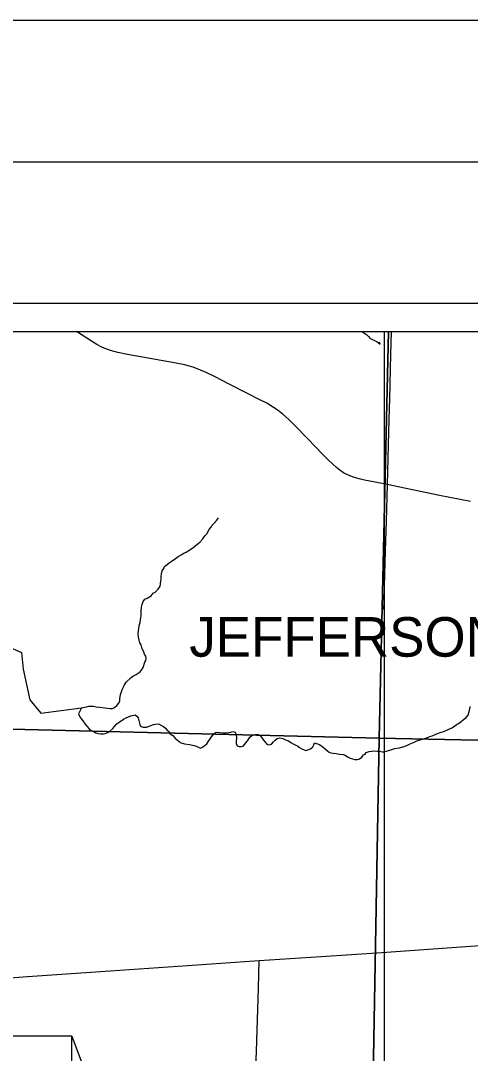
# Model space of a CAD drawing. Extents: x -21.9 to 47.3, y 14.1 to 48.7.
# Drawn here: x 4.214 to 5.806, y 45.08 to 48.733 of the extents above; entities that cross this region are included whole.
import ezdxf

# ---------------------------------------------------------------- set-up
doc = ezdxf.new("R2010")
doc.units = 0
for name, color, linetype in [('Default', 7, 'Continuous'), ('GM_X_County_Road', 7, 'Continuous'), ('GM_X_Minor_River', 7, 'Continuous'), ('GM_X_Section', 7, 'Continuous'), ('GM_X_Township_Road', 7, 'Continuous'), ('GM_X_US_Route', 7, 'Continuous'), ('SC_Scratch1', 7, 'Continuous'), ('SH_Border', 7, 'Continuous'), ('SH_Cut_Line', 7, 'Continuous'), ('SH_Data', 7, 'Continuous'), ('SH_Text', 7, 'Continuous')]:
    doc.layers.add(name, color=color, linetype=linetype)

msp = doc.modelspace()

# ---------------------------------------------------------------- linework, layer by layer
at = {"layer": 'Default'}
msp.add_lwpolyline([(2.8572, 44.6473), (4.3955, 44.6473), (4.3955, 45.1408), (2.8572, 45.1408)], close=True, dxfattribs=at)
at = {"layer": 'GM_X_County_Road'}
for p, q in [((4.4644, 47.5992), (4.4115, 47.6334)), ((4.4836, 47.5878), (4.4644, 47.5992)), ((4.5011, 47.5786), (4.4836, 47.5878)), ((4.51, 47.5745), (4.5011, 47.5786)), ((4.5318, 47.566), (4.51, 47.5745)), ((4.558, 47.5589), (4.5318, 47.566)), ((4.592, 47.552), (4.558, 47.5589)), ((4.6788, 47.5365), (4.592, 47.552)), ((4.7643, 47.5213), (4.6788, 47.5365)), ((4.7948, 47.5152), (4.7643, 47.5213)), ((4.8074, 47.5123), (4.7948, 47.5152)), ((4.8249, 47.507), (4.8074, 47.5123)), ((4.8505, 47.4971), (4.8249, 47.507)), ((4.871, 47.4881), (4.8505, 47.4971)), ((4.9023, 47.4727), (4.871, 47.4881)), ((4.9522, 47.4474), (4.9023, 47.4727)), ((5.022, 47.412), (4.9522, 47.4474)), ((5.0586, 47.3935), (5.022, 47.412)), ((5.0849, 47.3795), (5.0586, 47.3935)), ((5.1053, 47.3674), (5.0849, 47.3795)), ((5.125, 47.3541), (5.1053, 47.3674)), ((5.1436, 47.3394), (5.125, 47.3541)), ((5.163, 47.3218), (5.1436, 47.3394)), ((5.1871, 47.2984), (5.163, 47.3218)), ((5.2272, 47.2576), (5.1871, 47.2984)), ((5.2615, 47.2217), (5.2272, 47.2576)), ((5.2805, 47.202), (5.2615, 47.2217)), ((5.3024, 47.18), (5.2805, 47.202)), ((5.3193, 47.1637), (5.3024, 47.18)), ((5.3313, 47.153), (5.3193, 47.1637)), ((5.3437, 47.1429), (5.3313, 47.153)), ((5.357, 47.1339), (5.3437, 47.1429)), ((5.3633, 47.1302), (5.357, 47.1339)), ((5.3787, 47.1226), (5.3633, 47.1302)), ((5.3961, 47.1166), (5.3787, 47.1226)), ((5.4116, 47.1123), (5.3961, 47.1166)), ((5.4309, 47.1079), (5.4116, 47.1123)), ((5.5118, 47.0922), (5.4309, 47.1079)), ((5.5276, 47.0889), (5.5118, 47.0922)), ((5.6966, 47.0538), (5.5276, 47.0889)), ((5.8064, 47.0323), (5.6966, 47.0538))]:
    msp.add_line(p, q, dxfattribs=at)
at = {"layer": 'GM_X_Minor_River'}
for p, q in [((5.4218, 47.6334), (5.4387, 47.622)), ((5.4387, 47.622), (5.4446, 47.6165)), ((5.4446, 47.6165), (5.4512, 47.6094)), ((5.4512, 47.6094), (5.4572, 47.607)), ((5.4572, 47.607), (5.4684, 47.6005)), ((5.4684, 47.6005), (5.4744, 47.598)), ((5.4744, 47.598), (5.4862, 47.5885)), ((5.4862, 47.5885), (5.4841, 47.5954)), ((4.8915, 46.9487), (4.8993, 46.956)), ((4.8993, 46.956), (4.908, 46.9664)), ((4.908, 46.9664), (4.9136, 46.9746)), ((4.866, 46.9107), (4.8746, 46.9188)), ((4.8746, 46.9188), (4.8803, 46.9315)), ((4.8803, 46.9315), (4.8867, 46.9405)), ((4.8867, 46.9405), (4.8915, 46.9487)), ((4.8306, 46.8739), (4.8376, 46.8797)), ((4.8376, 46.8797), (4.8478, 46.8885)), ((4.8478, 46.8885), (4.8588, 46.9003)), ((4.8588, 46.9003), (4.866, 46.9107)), ((4.771, 46.837), (4.7818, 46.8435)), ((4.7818, 46.8435), (4.7919, 46.8493)), ((4.7919, 46.8493), (4.7996, 46.8528)), ((4.7996, 46.8528), (4.8073, 46.8579)), ((4.8073, 46.8579), (4.8229, 46.8688)), ((4.8229, 46.8688), (4.8306, 46.8739)), ((4.7228, 46.8021), (4.7321, 46.8087)), ((4.7321, 46.8087), (4.7391, 46.8153)), ((4.7391, 46.8153), (4.7461, 46.8204)), ((4.7461, 46.8204), (4.7617, 46.8305)), ((4.7617, 46.8305), (4.771, 46.837)), ((4.7118, 46.7667), (4.7128, 46.7758)), ((4.7128, 46.7758), (4.7147, 46.7864)), ((4.7147, 46.7864), (4.7203, 46.7946)), ((4.7203, 46.7946), (4.7228, 46.8021)), ((4.7004, 46.7222), (4.7076, 46.7326)), ((4.7076, 46.7326), (4.7104, 46.75)), ((4.7104, 46.75), (4.7114, 46.7569)), ((4.7114, 46.7569), (4.7118, 46.7667)), ((4.6622, 46.69), (4.6754, 46.6987)), ((4.6754, 46.6987), (4.6833, 46.7076)), ((4.6833, 46.7076), (4.6902, 46.7111)), ((4.6902, 46.7111), (4.7004, 46.7222)), ((4.6422, 46.658), (4.644, 46.6678)), ((4.644, 46.6678), (4.6474, 46.6783)), ((4.6474, 46.6783), (4.653, 46.6865)), ((4.653, 46.6865), (4.6622, 46.69)), ((4.6394, 46.6208), (4.6404, 46.6276)), ((4.6404, 46.6276), (4.641, 46.6451)), ((4.641, 46.6451), (4.6422, 46.658)), ((4.6321, 46.5837), (4.6341, 46.5966)), ((4.6341, 46.5966), (4.6366, 46.6041)), ((4.6366, 46.6041), (4.6385, 46.6147)), ((4.6385, 46.6147), (4.6394, 46.6208)), ((4.63, 46.564), (4.6311, 46.5746)), ((4.6311, 46.5518), (4.63, 46.564)), ((4.6311, 46.5746), (4.6321, 46.5837)), ((4.633, 46.5419), (4.6311, 46.5518)), ((4.1656, 46.5198), (4.2174, 46.4977)), ((4.6358, 46.5326), (4.633, 46.5419)), ((4.6401, 46.5256), (4.6358, 46.5326)), ((4.6441, 46.5103), (4.6401, 46.5256)), ((4.2174, 46.4977), (4.223, 46.4384)), ((4.6484, 46.5025), (4.6441, 46.5103)), ((4.6527, 46.4925), (4.6484, 46.5025)), ((4.657, 46.4848), (4.6527, 46.4925)), ((4.6565, 46.4696), (4.6582, 46.4771)), ((4.6582, 46.4771), (4.657, 46.4848)), ((4.6417, 46.4351), (4.6473, 46.4448)), ((4.6473, 46.4448), (4.6532, 46.4636)), ((4.6532, 46.4636), (4.6565, 46.4696)), ((4.223, 46.4384), (4.2459, 46.3304)), ((4.5879, 46.3927), (4.6044, 46.4081)), ((4.6044, 46.4081), (4.6114, 46.414)), ((4.6114, 46.414), (4.6222, 46.4205)), ((4.6222, 46.4205), (4.63, 46.4248)), ((4.63, 46.4248), (4.6361, 46.4284)), ((4.6361, 46.4284), (4.6417, 46.4351)), ((4.5725, 46.3628), (4.5751, 46.3718)), ((4.5751, 46.3718), (4.5807, 46.3808)), ((4.5807, 46.3808), (4.5879, 46.3927)), ((4.2459, 46.3304), (4.285, 46.2827)), ((4.5645, 46.3273), (4.5648, 46.3349)), ((4.5648, 46.3349), (4.5657, 46.3409)), ((4.5657, 46.3409), (4.5675, 46.3493)), ((4.5675, 46.3493), (4.5725, 46.3628)), ((4.285, 46.2827), (4.4294, 46.3021)), ((4.4294, 46.3021), (4.4181, 46.2804)), ((4.4294, 46.3021), (4.447, 46.3061)), ((4.447, 46.3061), (4.4554, 46.3081)), ((4.4554, 46.3081), (4.4637, 46.3086)), ((4.4637, 46.3086), (4.4713, 46.3076)), ((4.4713, 46.3076), (4.4811, 46.3057)), ((4.4811, 46.3057), (4.4947, 46.3045)), ((4.4947, 46.3045), (4.5114, 46.3024)), ((4.5114, 46.3024), (4.5212, 46.3006)), ((4.5212, 46.3006), (4.531, 46.2995)), ((4.531, 46.2995), (4.5386, 46.2992)), ((4.5386, 46.2992), (4.5455, 46.3028)), ((4.5455, 46.3028), (4.5549, 46.3109)), ((4.5549, 46.3109), (4.5612, 46.319)), ((4.5612, 46.319), (4.5645, 46.3273)), ((5.7975, 46.2756), (5.8026, 46.2937)), ((5.8026, 46.2937), (5.8045, 46.3043)), ((5.8045, 46.3043), (5.8048, 46.307)), ((4.4181, 46.2804), (4.4238, 46.2703)), ((4.4238, 46.2703), (4.4296, 46.2625)), ((4.4296, 46.2625), (4.4339, 46.2556)), ((4.5698, 46.2556), (4.5783, 46.2622)), ((4.5783, 46.2622), (4.5868, 46.2664)), ((4.5868, 46.2664), (4.596, 46.2699)), ((4.596, 46.2699), (4.6037, 46.2735)), ((4.6037, 46.2735), (4.619, 46.2775)), ((4.619, 46.2775), (4.6257, 46.2728)), ((4.6257, 46.2728), (4.6293, 46.2665)), ((4.6293, 46.2665), (4.6334, 46.2527)), ((5.7732, 46.2543), (5.7818, 46.2609)), ((5.7818, 46.2609), (5.7912, 46.2682)), ((5.7912, 46.2682), (5.7975, 46.2756)), ((4.4339, 46.2556), (4.4419, 46.2439)), ((4.4419, 46.2439), (4.4477, 46.2368)), ((4.4477, 46.2368), (4.4565, 46.2274)), ((4.4565, 46.2274), (4.4632, 46.2219)), ((4.4632, 46.2219), (4.4736, 46.2169)), ((4.5299, 46.2196), (4.5401, 46.2292)), ((4.5401, 46.2292), (4.5456, 46.2359)), ((4.5456, 46.2359), (4.5543, 46.2455)), ((4.5543, 46.2455), (4.5605, 46.2498)), ((4.5605, 46.2498), (4.5698, 46.2556)), ((4.6334, 46.2527), (4.6354, 46.2435)), ((4.6354, 46.2435), (4.6382, 46.2373)), ((4.6382, 46.2373), (4.6464, 46.2333)), ((4.6464, 46.2333), (4.6593, 46.2336)), ((4.6593, 46.2336), (4.6693, 46.2371)), ((4.6693, 46.2371), (4.6847, 46.2426)), ((4.6847, 46.2426), (4.6916, 46.2439)), ((4.6916, 46.2439), (4.7015, 46.2451)), ((4.7015, 46.2451), (4.7127, 46.2394)), ((4.7127, 46.2394), (4.7194, 46.2362)), ((4.7194, 46.2362), (4.726, 46.2306)), ((4.726, 46.2306), (4.7326, 46.2235)), ((4.7326, 46.2235), (4.7385, 46.218)), ((5.7121, 46.2183), (5.7268, 46.2254)), ((5.7268, 46.2254), (5.7406, 46.2318)), ((5.7406, 46.2318), (5.7491, 46.2369)), ((5.7491, 46.2369), (5.7569, 46.2427)), ((5.7569, 46.2427), (5.7631, 46.2471)), ((5.7631, 46.2471), (5.7732, 46.2543)), ((4.4736, 46.2169), (4.4796, 46.2137)), ((4.4796, 46.2137), (4.4879, 46.2119)), ((4.4879, 46.2119), (4.4969, 46.2101)), ((4.4969, 46.2101), (4.5068, 46.2105)), ((4.5068, 46.2105), (4.5167, 46.2125)), ((4.5167, 46.2125), (4.5229, 46.2145)), ((4.5229, 46.2145), (4.5299, 46.2196)), ((4.7385, 46.218), (4.7436, 46.2102)), ((4.7436, 46.2102), (4.7525, 46.2039)), ((4.7525, 46.2039), (4.7613, 46.1944)), ((4.7613, 46.1944), (4.7694, 46.1873)), ((4.7694, 46.1873), (4.7753, 46.1833)), ((4.7753, 46.1833), (4.782, 46.1778)), ((4.8729, 46.1747), (4.8793, 46.1844)), ((4.8793, 46.1844), (4.8841, 46.1926)), ((4.8841, 46.1926), (4.8897, 46.1993)), ((4.8897, 46.1993), (4.8944, 46.206)), ((4.8944, 46.206), (4.8984, 46.2119)), ((4.8984, 46.2119), (4.9054, 46.2155)), ((4.9054, 46.2155), (4.919, 46.2151)), ((4.919, 46.2151), (4.9319, 46.2139)), ((4.9319, 46.2139), (4.9395, 46.2136)), ((4.9395, 46.2136), (4.9509, 46.2148)), ((4.9509, 46.2148), (4.9578, 46.216)), ((4.9578, 46.216), (4.9647, 46.2189)), ((4.9647, 46.2189), (4.9729, 46.2163)), ((4.9729, 46.2163), (4.9764, 46.2063)), ((4.9764, 46.2063), (4.9784, 46.1963)), ((4.9772, 46.185), (4.9769, 46.1758)), ((4.9784, 46.1963), (4.9772, 46.185)), ((5.0112, 46.1785), (5.0174, 46.1851)), ((5.0174, 46.1851), (5.0215, 46.1919)), ((5.0215, 46.1919), (5.0247, 46.1978)), ((5.0247, 46.1978), (5.0317, 46.2045)), ((5.0317, 46.2045), (5.0455, 46.2078)), ((5.0455, 46.2078), (5.0546, 46.2075)), ((5.0546, 46.2075), (5.0628, 46.2027)), ((5.0628, 46.2027), (5.0679, 46.1964)), ((5.0679, 46.1964), (5.0737, 46.1878)), ((5.0737, 46.1878), (5.0788, 46.1808)), ((5.1084, 46.1814), (5.1147, 46.188)), ((5.1147, 46.188), (5.1217, 46.1938)), ((5.1217, 46.1938), (5.1309, 46.1958)), ((5.1309, 46.1958), (5.1422, 46.1932)), ((5.1422, 46.1932), (5.1511, 46.1891)), ((5.1511, 46.1891), (5.1616, 46.1849)), ((5.1616, 46.1849), (5.1705, 46.1793)), ((5.6038, 46.1793), (5.6162, 46.1858)), ((5.6162, 46.1858), (5.6284, 46.1884)), ((5.6284, 46.1884), (5.6361, 46.1912)), ((5.6361, 46.1912), (5.6476, 46.1946)), ((5.6476, 46.1946), (5.6561, 46.1981)), ((5.6561, 46.1981), (5.6622, 46.2002)), ((5.6622, 46.2002), (5.6699, 46.203)), ((5.6699, 46.203), (5.6807, 46.208)), ((5.6807, 46.208), (5.6891, 46.2115)), ((5.6891, 46.2115), (5.7022, 46.2156)), ((5.7022, 46.2156), (5.7121, 46.2183)), ((4.782, 46.1778), (4.7933, 46.1751)), ((4.7933, 46.1751), (4.8121, 46.1722)), ((4.8121, 46.1722), (4.8279, 46.1686)), ((4.8279, 46.1686), (4.8347, 46.1669)), ((4.8347, 46.1669), (4.8415, 46.1644)), ((4.8415, 46.1644), (4.8497, 46.1595)), ((4.8497, 46.1595), (4.8574, 46.1631)), ((4.8574, 46.1631), (4.8667, 46.1696)), ((4.8667, 46.1696), (4.8729, 46.1747)), ((4.9769, 46.1758), (4.9797, 46.1681)), ((4.9797, 46.1681), (4.9872, 46.1656)), ((4.9872, 46.1656), (4.994, 46.1654)), ((4.994, 46.1654), (5.0009, 46.1667)), ((5.0009, 46.1667), (5.0112, 46.1785)), ((5.0788, 46.1808), (5.0854, 46.1738)), ((5.0854, 46.1738), (5.0921, 46.1712)), ((5.0921, 46.1712), (5.1013, 46.174)), ((5.1013, 46.174), (5.1084, 46.1814)), ((5.1705, 46.1793), (5.181, 46.1736)), ((5.181, 46.1736), (5.1877, 46.1703)), ((5.1877, 46.1703), (5.1937, 46.1671)), ((5.1937, 46.1671), (5.2011, 46.1623)), ((5.2011, 46.1623), (5.2093, 46.1575)), ((5.2093, 46.1575), (5.2175, 46.1534)), ((5.2175, 46.1534), (5.2235, 46.1517)), ((5.2235, 46.1517), (5.2304, 46.1537)), ((5.2304, 46.1537), (5.2396, 46.1572)), ((5.2396, 46.1572), (5.2482, 46.1638)), ((5.2482, 46.1638), (5.2515, 46.1713)), ((5.2515, 46.1713), (5.254, 46.178)), ((5.254, 46.178), (5.2713, 46.1729)), ((5.2713, 46.1729), (5.2846, 46.1626)), ((5.2846, 46.1626), (5.3001, 46.1499)), ((5.3001, 46.1499), (5.306, 46.1451)), ((5.4373, 46.1445), (5.4472, 46.148)), ((5.4472, 46.148), (5.4564, 46.1492)), ((5.4564, 46.1492), (5.464, 46.1505)), ((5.464, 46.1505), (5.4754, 46.1494)), ((5.4754, 46.1494), (5.4844, 46.1483)), ((5.4844, 46.1483), (5.4942, 46.1464)), ((5.5003, 46.1462), (5.5087, 46.149)), ((5.5087, 46.149), (5.5164, 46.151)), ((5.5164, 46.151), (5.5271, 46.1545)), ((5.5271, 46.1545), (5.5386, 46.1579)), ((5.5386, 46.1579), (5.5455, 46.1592)), ((5.5455, 46.1592), (5.5554, 46.1611)), ((5.5554, 46.1611), (5.5615, 46.1625)), ((5.5615, 46.1625), (5.5677, 46.1645)), ((5.5677, 46.1645), (5.5807, 46.1694)), ((5.5807, 46.1694), (5.5931, 46.1751)), ((5.5931, 46.1751), (5.6038, 46.1793)), ((5.306, 46.1451), (5.312, 46.1426)), ((5.312, 46.1426), (5.3196, 46.1416)), ((5.3196, 46.1416), (5.3301, 46.1405)), ((5.3301, 46.1405), (5.3362, 46.1395)), ((5.3362, 46.1395), (5.3437, 46.1385)), ((5.3437, 46.1385), (5.3558, 46.1366)), ((5.3558, 46.1366), (5.3626, 46.1341)), ((5.3626, 46.1341), (5.3707, 46.1293)), ((5.3707, 46.1293), (5.3804, 46.1236)), ((5.3804, 46.1236), (5.3879, 46.1211)), ((5.3879, 46.1211), (5.3962, 46.1193)), ((5.3962, 46.1193), (5.4061, 46.1189)), ((5.4061, 46.1189), (5.413, 46.1218)), ((5.413, 46.1218), (5.4215, 46.1276)), ((5.4215, 46.1276), (5.4271, 46.1357)), ((5.4271, 46.1357), (5.4333, 46.1386)), ((5.4333, 46.1386), (5.4373, 46.1445)), ((5.4942, 46.1464), (5.5003, 46.1462))]:
    msp.add_line(p, q, dxfattribs=at)
at = {"layer": 'GM_X_Section'}
for p, q in [((5.5158, 47.6334), (5.4826, 46.1948)), ((5.4826, 46.1948), (5.5158, 47.6334)), ((5.4826, 46.1948), (3.4698, 46.2442)), ((3.4698, 46.2442), (5.4826, 46.1948)), ((5.4826, 46.1948), (5.4472, 44.1627)), ((5.4472, 44.1627), (5.4826, 46.1948)), ((7.4871, 46.1518), (5.4826, 46.1948)), ((5.4826, 46.1948), (7.4871, 46.1518))]:
    msp.add_line(p, q, dxfattribs=at)
at = {"layer": 'GM_X_Township_Road'}
for p, q in [((5.5241, 47.5526), (5.5261, 47.6334)), ((5.5206, 47.3962), (5.5241, 47.5526)), ((5.5185, 47.323), (5.5206, 47.3962)), ((5.5118, 47.0922), (5.5185, 47.323)), ((5.5084, 46.9629), (5.5118, 47.0922)), ((5.5053, 46.8561), (5.5084, 46.9629)), ((5.5016, 46.7319), (5.5053, 46.8561)), ((5.501, 46.6777), (5.5016, 46.7319)), ((5.4967, 46.6514), (5.4996, 46.6589)), ((5.4996, 46.6589), (5.5006, 46.6684)), ((5.5006, 46.6684), (5.501, 46.6777)), ((5.0561, 45.31), (5.0578, 45.4078)), ((5.0485, 45.0879), (5.0561, 45.31)), ((5.0426, 44.9315), (5.0485, 45.0879))]:
    msp.add_line(p, q, dxfattribs=at)
at = {"layer": 'GM_X_US_Route'}
for p, q in [((5.4924, 45.4366), (5.9411, 45.4692)), ((5.0578, 45.4078), (5.2779, 45.422)), ((5.2779, 45.422), (5.4924, 45.4366)), ((4.5303, 45.3713), (4.8043, 45.3904)), ((4.8043, 45.3904), (5.0578, 45.4078)), ((3.9762, 45.333), (4.2378, 45.3511)), ((4.2378, 45.3511), (4.5303, 45.3713))]:
    msp.add_line(p, q, dxfattribs=at)
at = {"layer": 'SC_Scratch1'}
msp.add_line((5.5, 47.6334), (5.5, 40.8334), dxfattribs=at)
at = {"layer": 'SH_Border'}
msp.add_lwpolyline([(1.5, 48.2334), (33.5, 48.2334), (33.5, 27.2334), (1.5, 27.2334)], close=True, dxfattribs=at)
at = {"layer": 'SH_Cut_Line'}
msp.add_lwpolyline([(0, 26.7334), (34, 26.7334), (34, 48.7334), (0, 48.7334)], close=True, dxfattribs=at)
at = {"layer": 'SH_Data'}
for p, q in [((2, 47.7334), (9, 47.7334)), ((2.1, 47.6334), (8.9, 47.6334))]:
    msp.add_line(p, q, dxfattribs=at)
at = {"layer": 'SH_Text'}
msp.add_lwpolyline([(4.7267, 44.2546), (4.3955, 44.6473), (4.3955, 45.1408)], close=True, dxfattribs=at)

# ---------------------------------------------------------------- texts
msp.add_text('JEFFERSON TWP.', height=0.14, dxfattribs=at).set_placement((4.811, 46.4831))

doc.saveas('drawing.dxf')
